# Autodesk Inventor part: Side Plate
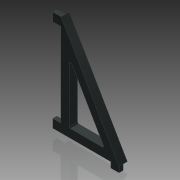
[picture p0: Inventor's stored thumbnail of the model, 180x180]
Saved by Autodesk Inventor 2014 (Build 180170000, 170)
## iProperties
Created: 2015-07
Part Number: Side Plate
Material: Generic
Document SubType Name: Modeling
Designer: Brad Factor
Density: 1 g/cm^3
Appearance: Gunmetal - Polished
Author: Brad Factor
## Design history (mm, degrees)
sketch "Sketch1"
  geometry: L1 (0, 0)-(0, 115.418); L2 (0, 115.418)-(66.636, 0); L3 (66.636, 0)-(0, 0); L4 (50.139, 9.525)-(9.525, 79.87); L5 (9.525, 79.87)-(9.525, 9.525); L6 (9.525, 9.525)-(50.139, 9.525)
  constraints: 12 end point, 1 horizontal, 1 vertical, 2 other
  dimensions: "d0" = 115.4176 distance of L1.start L1.end; "d1" = 30 deg angle of L2 L1; "d2" = 9.525 distance between parallel lines of L3 L6
extrude "Plate" new body sketch "Sketch1" distance "d3" = 9.525; taper "d4" = 0 deg
sketch "Sketch2"
  geometry: L1 (0, 0)-(0, 115.418) reference; L2 (0, 115.418)-(-4.763, 115.418); L3 (-4.763, 115.418)-(-4.763, 105.893); L4 (-4.763, 105.893)-(0, 105.893); L5 (0, 105.893)-(0, 115.418); L6 (0, 0)-(-4.762, 0); L7 (-4.762, 0)-(-4.762, 9.525); L8 (-4.762, 9.525)-(0, 9.525); L9 (0, 9.525)-(0, 0)
  constraints: 16 end point, 4 parallel, 2 horizontal, 2 perpendicular
  dimensions: "d5" = 9.525 distance of L2.end L3.end; "d6" = 4.7625 distance between parallel lines of L1 L3; "d7" = 9.525 distance of L6.end L7.end; "d8" = 4.7625 distance of L7.end L8.end
extrude "Assembly Horizontal Tabs" join sketch "Sketch2" distance "d9" = 9.525; taper "d10" = 0 deg
sketch "Sketch3"
  geometry: L1 (66.636, 9.525)-(57.111, 9.525); L2 (57.111, 9.525)-(57.111, 4.762); L3 (57.111, 4.762)-(66.636, 4.763); L4 (66.636, 4.763)-(66.636, 9.525); 1 further point
  constraints: 8 end point, 2 parallel, 1 horizontal, 1 perpendicular
  dimensions: "d11" = 9.525 distance of L2.end L3.end; "d12" = 4.7625 distance of L1.end L2.end
extrude "Assembly Vertical Tab" join sketch "Sketch3" distance "d13" = 6.35; taper "d14" = 0 deg
fillet "1/16\" Fillets" dims "d15" = 1.5875
body "Solid1"
